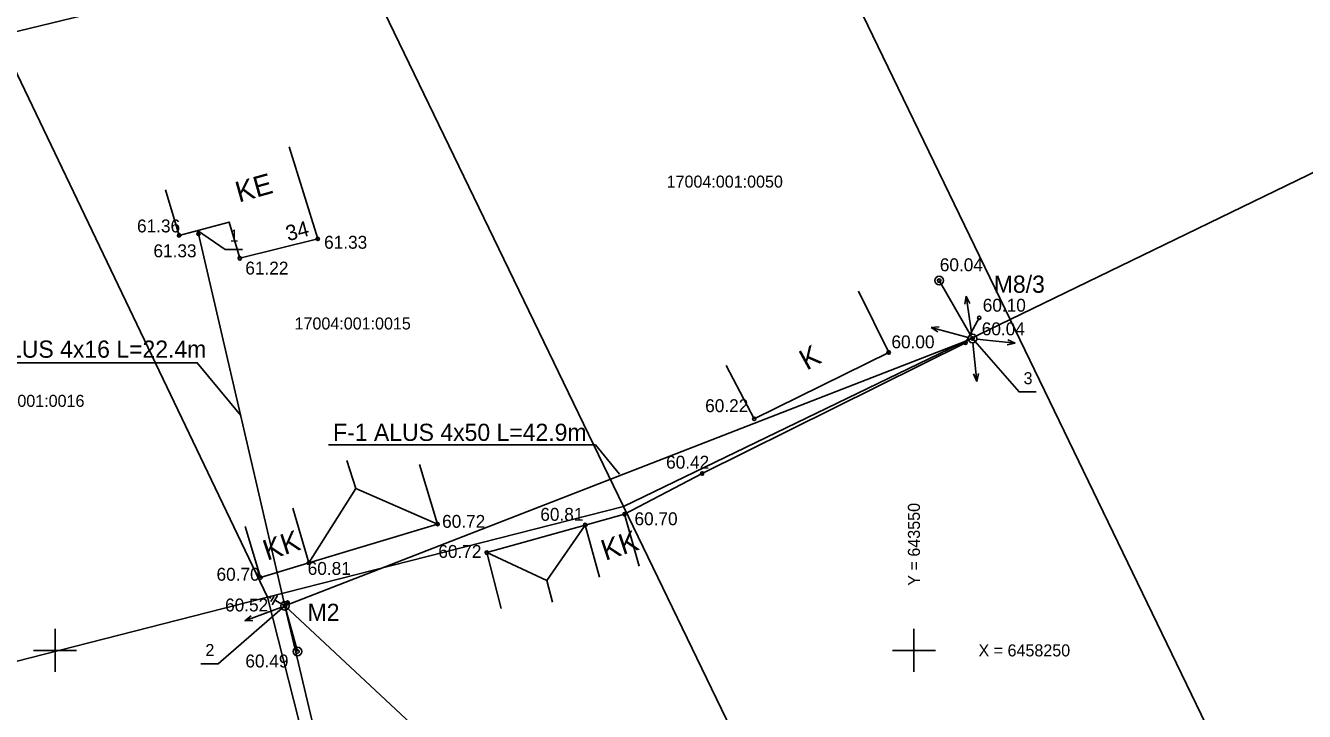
# Model space of a CAD drawing. Extents: x 643307 to 644029, y 6457938 to 6458417.
# Drawn here: x 643498.3 to 643572.7, y 6458246.5 to 6458286.3 of the extents above; entities that cross this region are included whole.
import ezdxf

# ---------------------------------------------------------------- set-up
doc = ezdxf.new("R2010")
doc.units = 0
for name, color, linetype in [('11_KTRASS', 7, 'Continuous'), ('14_MPOHULIIN', 7, 'Continuous'), ('15_MPKAABEL', 7, 'Continuous'), ('1_HOONE', 7, 'Continuous'), ('26_POST', 7, 'Continuous'), ('28_AED', 7, 'Continuous'), ('30_TEE', 7, 'Continuous'), ('3_RAJATIS', 7, 'Continuous'), ('40_PIIR', 7, 'Continuous'), ('59_KORGUS', 7, 'Continuous'), ('62_MOOTMPUNKT', 7, 'Continuous'), ('63_VORK', 7, 'Continuous'), ('Level 25', 7, 'Continuous'), ('Level 32', 7, 'Continuous'), ('Level 55', 7, 'Continuous')]:
    doc.layers.add(name, color=color, linetype=linetype)

# ---------------------------------------------------------------- blocks, each defined once
blk = doc.blocks.new('RING02')
at = {"layer": '59_KORGUS'}
blk.add_circle((0, 0), 0.2, dxfattribs=at)
blk = doc.blocks.new('PUPOST')
at = {"layer": '26_POST'}
blk.add_circle((0, 0), 0.5, dxfattribs=at)
blk = doc.blocks.new('MAANDU')
at = {"layer": 'Level 32'}
for points in [[(0, 0), (0, -1.36)], [(0.64, -1.37), (-0.64, -1.37)], [(0.37, -1.67), (-0.37, -1.67)], [(0.1, -1.97), (-0.1, -1.97)]]:
    blk.add_lwpolyline(points, dxfattribs=at)
blk = doc.blocks.new('TUPOST')
at = {"layer": '11_KTRASS'}
blk.add_circle((0, 0), 0.5, dxfattribs=at)
blk = doc.blocks.new('MPSUUN')
at = {"layer": '14_MPOHULIIN'}
for p, q in [((0, 0), (0, 0)), ((0.5, 0), (5, 0)), ((5, 0), (4.1, 0.3)), ((5, 0), (4.1, -0.3))]:
    blk.add_line(p, q, dxfattribs=at)
blk = doc.blocks.new('VKORIS')
at = {"layer": '30_TEE'}
for p, q in [((0, 2.5), (0, -2.5)), ((-2.5, 0), (2.5, 0))]:
    blk.add_line(p, q, dxfattribs=at)

msp = doc.modelspace()

# ---------------------------------------------------------------- linework, layer by layer
at = {"layer": '14_MPOHULIIN'}
msp.add_line((643513.386, 6458252.587), (643553.408, 6458268.132), dxfattribs=at)
for points in [[(643508.301, 6458274.42), (643508.347, 6458274.224), (643513.386, 6458252.587)], [(643513.386, 6458252.587), (643522.173, 6458244.382), (643530.959, 6458236.177)], [(643513.386, 6458252.587), (643521.823, 6458217)], [(643513.386, 6458252.587), (643521.823, 6458217)], [(643513.386, 6458252.587), (643521.823, 6458217)]]:
    msp.add_lwpolyline(points, dxfattribs=at)
at = {"layer": '1_HOONE'}
for p, q in [((643540.705, 6458263.468), (643539.066, 6458266.568)), ((643533.148, 6458257.922), (643534.001, 6458254.904))]:
    msp.add_line(p, q, dxfattribs=at)
for points in [[(643513.634, 6458279.29), (643515.293, 6458273.931), (643510.758, 6458272.801), (643510.141, 6458274.906), (643507.222, 6458274.135), (643506.433, 6458276.791)], [(643540.705, 6458263.468), (643548.531, 6458267.321), (643546.777, 6458270.886)], [(643533.148, 6458257.922), (643530.859, 6458257.29), (643531.693, 6458254.267)], [(643514.78, 6458255.085), (643511.958, 6458254.24), (643511.072, 6458257.199)]]:
    msp.add_lwpolyline(points, dxfattribs=at)
at = {"layer": '26_POST'}
for p, q in [((643551.472, 6458271.504), (643553.408, 6458268.132)), ((643514.116, 6458249.933), (643513.386, 6458252.587))]:
    msp.add_line(p, q, dxfattribs=at)
at = {"layer": '28_AED'}
msp.add_line((643537.668, 6458260.287), (643533.148, 6458257.922), dxfattribs=at)
msp.add_lwpolyline([(643553.803, 6458269.337), (643553.005, 6458267.888), (643537.668, 6458260.287)], dxfattribs=at)
at = {"layer": '3_RAJATIS'}
for p, q in [((643517.506, 6458259.408), (643516.986, 6458261.038)), ((643514.78, 6458255.085), (643517.506, 6458259.408)), ((643522.269, 6458257.343), (643517.506, 6458259.408)), ((643514.78, 6458255.085), (643513.834, 6458258.277)), ((643525.135, 6458255.684), (643530.859, 6458257.29)), ((643530.859, 6458257.29), (643528.634, 6458254.069)), ((643525.135, 6458255.684), (643525.971, 6458252.426)), ((643525.135, 6458255.684), (643528.634, 6458254.069)), ((643528.634, 6458254.069), (643528.968, 6458252.801))]:
    msp.add_line(p, q, dxfattribs=at)
msp.add_lwpolyline([(643514.78, 6458255.085), (643522.269, 6458257.343), (643521.226, 6458260.803)], dxfattribs=at)
at = {"layer": '40_PIIR'}
for points in [[(643562.42, 6458312.54), (643539.91, 6458301.65), (643555.6, 6458269.25), (643578.1, 6458280.14)], [(643539.91, 6458301.65), (643517.41, 6458290.76), (643533.09, 6458258.36), (643555.6, 6458269.25)], [(643517.41, 6458290.76), (643496.71, 6458285.74), (643512.36, 6458253.09), (643533.09, 6458258.36)], [(643496.71, 6458285.74), (643479.33, 6458281.53), (643488.13, 6458246.92), (643512.36, 6458253.09)], [(643571.28, 6458236.85), (643593.78, 6458247.74), (643578.1, 6458280.14), (643555.6, 6458269.25)], [(643548.78, 6458225.97), (643571.28, 6458236.85), (643555.6, 6458269.25), (643533.09, 6458258.36)], [(643521.24, 6458218.21), (643548.78, 6458225.97), (643533.09, 6458258.36), (643512.36, 6458253.09)], [(643521.24, 6458218.21), (643512.36, 6458253.09), (643488.13, 6458246.92), (643497.06, 6458211.84)]]:
    msp.add_lwpolyline(points, close=True, dxfattribs=at)
at = {"layer": 'Level 25'}
for points in [[(643508.301, 6458274.42), (643509.905, 6458273.319), (643510.905, 6458273.319)], [(643553.408, 6458268.132), (643556.123, 6458265.029), (643557.123, 6458265.029)], [(643493.427, 6458266.73), (643508.275, 6458266.73), (643510.809, 6458263.653)], [(643515.927, 6458261.955), (643531.458, 6458261.955), (643532.857, 6458260.255)], [(643513.386, 6458252.587), (643509.492, 6458249.219), (643508.492, 6458249.219)]]:
    msp.add_lwpolyline(points, dxfattribs=at)
at = {"layer": 'Level 55'}
for p, q in [((643507.222, 6458274.135), (643507.222, 6458274.135)), ((643508.347, 6458274.224), (643508.347, 6458274.224)), ((643515.293, 6458273.931), (643515.293, 6458273.931)), ((643510.758, 6458272.801), (643510.758, 6458272.801)), ((643551.472, 6458271.504), (643551.472, 6458271.504)), ((643553.803, 6458269.337), (643553.803, 6458269.337)), ((643553.005, 6458267.888), (643553.005, 6458267.888)), ((643553.408, 6458268.132), (643553.408, 6458268.132)), ((643548.531, 6458267.321), (643548.531, 6458267.321)), ((643540.705, 6458263.468), (643540.705, 6458263.468)), ((643537.668, 6458260.287), (643537.668, 6458260.287)), ((643533.148, 6458257.922), (643533.148, 6458257.922)), ((643522.269, 6458257.343), (643522.269, 6458257.343)), ((643530.859, 6458257.29), (643530.859, 6458257.29)), ((643525.135, 6458255.684), (643525.135, 6458255.684)), ((643514.78, 6458255.085), (643514.78, 6458255.085)), ((643511.958, 6458254.24), (643511.958, 6458254.24)), ((643513.386, 6458252.587), (643513.386, 6458252.587)), ((643513.537, 6458252.778), (643513.537, 6458252.778)), ((643514.116, 6458249.933), (643514.116, 6458249.933))]:
    msp.add_line(p, q, dxfattribs=at)

# ---------------------------------------------------------------- block references
at = {"layer": '14_MPOHULIIN', "xscale": 0.5}
for p, yscale, rotation in [((643553.408, 6458268.132), 0.49999999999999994, 98.47253976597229), ((643553.408, 6458268.132), 0.5, 164.93645831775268), ((643553.408, 6458268.132), 0.5, -84.32428436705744), ((643553.408, 6458268.132), 0.49999999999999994, -5.91719098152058), ((643513.386, 6458252.587), 0.5, -159.5120888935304)]:
    msp.add_blockref('MPSUUN', p, dxfattribs=dict(at, yscale=yscale, rotation=rotation))
at = {"layer": '15_MPKAABEL', "xscale": 0.5, "yscale": 0.5, "rotation": -119.25889657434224}
msp.add_blockref('MAANDU', (643513.386, 6458252.587), dxfattribs=at)
at = {"layer": '26_POST', "xscale": 0.5, "yscale": 0.5}
for name, p in [('TUPOST', (643551.472, 6458271.504)), ('PUPOST', (643553.408, 6458268.132)), ('PUPOST', (643513.386, 6458252.587)), ('TUPOST', (643514.116, 6458249.933))]:
    msp.add_blockref(name, p, dxfattribs=at)
at = {"layer": '62_MOOTMPUNKT', "xscale": 0.5, "yscale": 0.5}
for p in [(643507.222, 6458274.135), (643508.347, 6458274.224), (643515.293, 6458273.931), (643510.758, 6458272.801), (643551.472, 6458271.504), (643553.803, 6458269.337), (643553.005, 6458267.888), (643553.408, 6458268.132), (643548.531, 6458267.321), (643540.705, 6458263.468), (643537.668, 6458260.287), (643522.269, 6458257.343), (643530.859, 6458257.29), (643533.148, 6458257.922), (643514.78, 6458255.085), (643525.135, 6458255.684), (643511.958, 6458254.24), (643513.386, 6458252.587), (643513.537, 6458252.778), (643514.116, 6458249.933)]:
    msp.add_blockref('RING02', p, dxfattribs=at)
at = {"layer": '63_VORK', "xscale": 0.5, "yscale": 0.5}
for p in [(643500, 6458250), (643550, 6458250)]:
    msp.add_blockref('VKORIS', p, dxfattribs=at)

# ---------------------------------------------------------------- texts
at = {"layer": '1_HOONE'}
for s, height, rotation, p in [('KE', 1.2, 15.6603, (643510.702, 6458276.042)), ('34', 0.9, 14.96672, (643513.566, 6458273.789)), ('K', 1.2, 28.77897, (643543.758, 6458266.258)), ('KK', 1.2, 18.27095, (643512.348, 6458255.208)), ('KK', 1.2, 18.27095, (643532.035, 6458255.208))]:
    msp.add_text(s, height=height, rotation=rotation, dxfattribs=at).set_placement(p)
at = {"layer": '40_PIIR'}
for s, p in [('17004:001:0050', (643535.604, 6458276.912)), ('17004:001:0015', (643513.944, 6458268.662)), ('17004:001:0016', (643494.944, 6458264.162))]:
    msp.add_text(s, height=0.7, dxfattribs=at).set_placement(p)
at = {"layer": '59_KORGUS'}
for s, p in [('61.36', (643504.773, 6458274.309)), ('61.33', (643515.664, 6458273.359)), ('61.33', (643505.729, 6458272.864)), ('61.22', (643511.077, 6458271.858)), ('60.04', (643551.506, 6458272.051)), ('60.10', (643554.006, 6458269.697)), ('60.04', (643553.949, 6458268.324)), ('60.00', (643548.69, 6458267.567)), ('60.22', (643537.847, 6458263.855)), ('60.42', (643535.573, 6458260.568)), ('60.81', (643528.25, 6458257.535)), ('60.72', (643522.534, 6458257.127)), ('60.70', (643533.733, 6458257.279)), ('60.72', (643522.313, 6458255.379)), ('60.81', (643514.708, 6458254.39)), ('60.70', (643509.402, 6458254.051)), ('60.52', (643509.898, 6458252.264)), ('60.49', (643511.08, 6458249.007))]:
    msp.add_text(s, height=0.75, dxfattribs=at).set_placement(p)
at = {"layer": '63_VORK'}
msp.add_text(' Y = 643550', height=0.7, rotation=90, dxfattribs=at).set_placement((643550.35, 6458253.5))
msp.add_text(' X = 6458250', height=0.7, dxfattribs=at).set_placement((643553.5, 6458249.65))
at = {"layer": 'Level 25'}
for s, height, p in [(' 1', 0.7, (643509.905, 6458273.769)), ('M8/3', 1, (643554.649, 6458270.797)), ('F-1 ALUS 4x16 L=22.4m', 1, (643494.052, 6458267.019)), (' 3', 0.7, (643556.123, 6458265.479)), ('F-1 ALUS 4x50 L=42.9m', 1, (643516.188, 6458262.181)), ('M2', 1, (643514.702, 6458251.712)), (' 2', 0.7, (643508.492, 6458249.669))]:
    msp.add_text(s, height=height, dxfattribs=at).set_placement(p)

doc.saveas('drawing.dxf')
